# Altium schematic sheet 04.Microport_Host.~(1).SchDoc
size A4; CheckedBy: <审核日期>; Author: 赵金生; CompanyName: 广州周立功单片机科技有限公司; DocumentNumber: 4; SheetNumber: 4; SheetTotal: 7; PageSetup: Record=PageOptions¦CenterHorizontal=True¦CenterVertical=True¦PrintScale=1.00¦XCorrection=1.00¦YCorrection=1.00¦PrintKind=0¦BorderSize=5000000¦LeftOffset=0¦BottomOffset=0¦Orientation=2¦PaperLength=1000¦PaperWidth=1000¦Scale=100¦PaperSource=7¦PrintQuality=600¦MediaType=1¦DitherType=10¦PaperKind=A4¦PrintScaleMode=1; DesignDate: 2016-12-29; CheckDate: <审核人员>; SheetName: MicroPort接口; SheetVersion: V1.01; SheetDescription: MicroPort接口; productModel: AM116-Core; productName: 开发套件
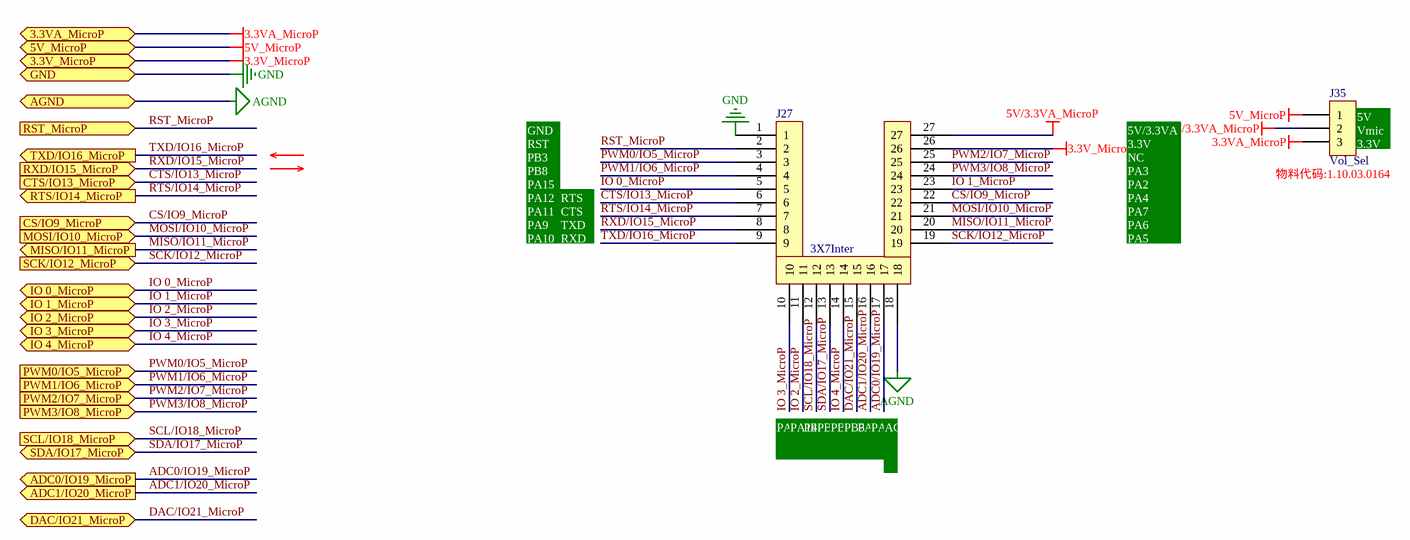
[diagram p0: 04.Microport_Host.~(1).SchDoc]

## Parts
J27  3X7Inter  [SIP-27 2.54C]
J35  Vol_Sel  [SIP-3-2.54]

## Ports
3.3V_MicroP, 3.3VA_MicroP, 5V_MicroP, ADC0/IO19_MicroP (out), ADC1/IO20_MicroP (out), AGND, CS/IO9_MicroP (in), CTS/IO13_MicroP (in), DAC/IO21_MicroP (bidir), GND, IO 0_MicroP (bidir), IO 1_MicroP (bidir), IO 2_MicroP (bidir), IO 3_MicroP (bidir), IO 4_MicroP (bidir), MISO/IO11_MicroP (out), MOSI/IO10_MicroP (in), PWM0/IO5_MicroP (in), PWM1/IO6_MicroP (in), PWM2/IO7_MicroP (in), PWM3/IO8_MicroP (in), RST_MicroP (in), RTS/IO14_MicroP (out), RXD/IO15_MicroP (in), SCK/IO12_MicroP (in), SCL/IO18_MicroP (in), SDA/IO17_MicroP (bidir), TXD/IO16_MicroP (out)

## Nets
3.3V_MicroP: J27.26 ; port 3.3V_MicroP
3.3VA_MicroP: J35.3 ; port 3.3VA_MicroP
5V/3.3VA_MicroP: J27.27 J35.2
5V_MicroP: J35.1 ; port 5V_MicroP
AGND: J27.18 ; port AGND
GND: J27.1 ; port GND
ADC0/IO19_MicroP: J27.17 ; port ADC0/IO19_MicroP
ADC1/IO20_MicroP: J27.16 ; port ADC1/IO20_MicroP
CS/IO9_MicroP: J27.22 ; port CS/IO9_MicroP
CTS/IO13_MicroP: J27.6 ; port CTS/IO13_MicroP
DAC/IO21_MicroP: J27.15 ; port DAC/IO21_MicroP
IO 0_MicroP: J27.5 ; port IO 0_MicroP
IO 1_MicroP: J27.23 ; port IO 1_MicroP
IO 2_MicroP: J27.11 ; port IO 2_MicroP
IO 3_MicroP: J27.10 ; port IO 3_MicroP
IO 4_MicroP: J27.14 ; port IO 4_MicroP
MISO/IO11_MicroP: J27.20 ; port MISO/IO11_MicroP
MOSI/IO10_MicroP: J27.21 ; port MOSI/IO10_MicroP
PWM0/IO5_MicroP: J27.3 ; port PWM0/IO5_MicroP
PWM1/IO6_MicroP: J27.4 ; port PWM1/IO6_MicroP
PWM2/IO7_MicroP: J27.25 ; port PWM2/IO7_MicroP
PWM3/IO8_MicroP: J27.24 ; port PWM3/IO8_MicroP
RST_MicroP: J27.2 ; port RST_MicroP
RTS/IO14_MicroP: J27.7 ; port RTS/IO14_MicroP
RXD/IO15_MicroP: J27.8 ; port RXD/IO15_MicroP
SCK/IO12_MicroP: J27.19 ; port SCK/IO12_MicroP
SCL/IO18_MicroP: J27.12 ; port SCL/IO18_MicroP
SDA/IO17_MicroP: J27.13 ; port SDA/IO17_MicroP
TXD/IO16_MicroP: J27.9 ; port TXD/IO16_MicroP

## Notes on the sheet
- (near J35) 物料代码:1.10.03.0164
- (near J35) 5V
- (near J35) Vmic
  3.3V
- GND
  RST
  PB3
  PB8
  PA15
  PA12
  PA11
  PA9
  PA10
- TXD
- RXD
- RTS
- CTS
- 5V/3.3VA
  3.3V
  NC
  PA3
  PA2
  PA4
  PA7
  PA6
  PA5
- PA13
- PA14
- PB6
- PB7
- PB4
- PB5
- PA0
- PA1
- AGND

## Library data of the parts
J27 = 3X7Inter: 物料代码: 1.10.11.0074
J35 = CON3: Connector; 物料代码: 1.10.03.0164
